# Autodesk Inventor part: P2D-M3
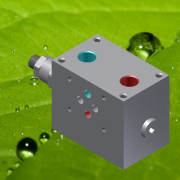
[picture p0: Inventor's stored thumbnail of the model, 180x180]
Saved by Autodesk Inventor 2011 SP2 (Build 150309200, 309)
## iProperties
Created: 2013-10
Part Number: P2D-M3
Document SubType Name: Modeling
Designer: dorohin
Density: 1 g/cm^3
Author: dorohin
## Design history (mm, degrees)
derived "P2D-M3_33.iam"
node "Твердое тело1"
node "0112965-01.ipt:1"
node "0570193.ipt:1"
node "0570182.ipt:1"
node "0112130.ipt:1"
node "0112125.ipt:1"
node "0532039.ipt:1"
